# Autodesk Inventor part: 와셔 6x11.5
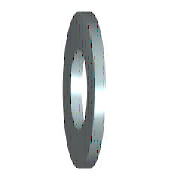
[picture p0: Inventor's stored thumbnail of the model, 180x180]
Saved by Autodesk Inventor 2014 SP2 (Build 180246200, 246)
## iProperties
IsCustomPart: 1
Created: 2012-02
Part Number: 와셔 6x11.5
Material: 강철, 연강
Description: 평면 와셔
Document SubType Name: Modeling
Standard: KS B 1326
Designer: mduedu
Standards Organization: KS
Language: ko-KR
Size Designation: 6x11.5
Categories: <MemberInstance><Categories><Category DisplayName="조임쇠" InternalName="e4da775c-781d-43d5-af7c-5136215cf5a6" Mnemonic="FSTN"><Category DisplayName="와셔" InternalN
Density: 1 g/cm^3
Appearance: 주황색
Author: mduedu
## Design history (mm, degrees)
sketch "스케치"
  geometry: C1 r 5.75 at (0, 0); C2 r 3.2 at (0, 0); 1 further point
  constraints: 2 centre point, 2 coincident
  dimensions: "d0" = 6.4 diameter of C2 (= SD1); "d1" = 11.5 diameter of C1 (= SD2)
extrude "본체" new body sketch "스케치" distance "d2" = 1.6 (= SD); taper "d3" = 0 deg
workaxis "Work Axis1"
workplane "Work Plane1"
body "Solid1"
other parameters: "SD1" = 6.4 [user parameter; used in 1 equation term], "SD2" = 11.5 [user parameter; used in 1 equation term], "SD" = 1.6 [user parameter; used in 1 equation term], "d4" = 0, "d5" = 0, "d6" = 0, "d7" = 0, "NND" = 6 [user parameter]
